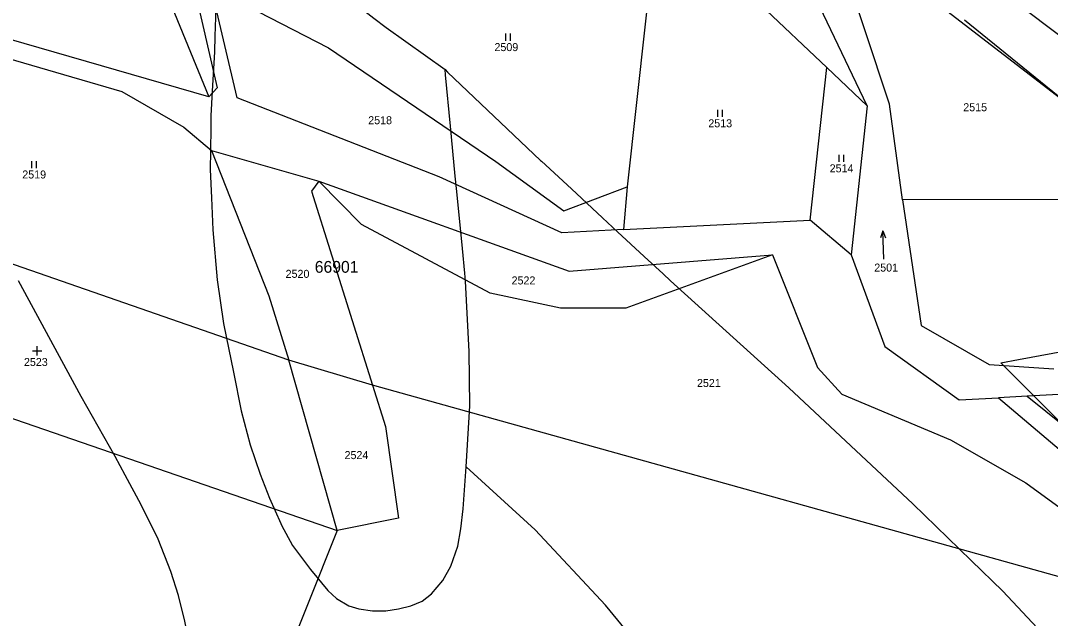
# Model space of a CAD drawing. Extents: x -546762 to -540209, y -1046851 to -1035694.
# Drawn here: x -542465 to -542246.2, y -1040002.5 to -1039875.5 of the extents above; entities that cross this region are included whole.
import ezdxf

# ---------------------------------------------------------------- set-up
doc = ezdxf.new("R2010")
doc.units = 0
for name, color, linetype in [('Vrstva 1', 7, 'Continuous'), ('Vrstva 18', 7, 'Continuous'), ('Vrstva 25', 7, 'Continuous'), ('Vrstva 52', 7, 'Continuous'), ('Vrstva 53', 7, 'Continuous')]:
    doc.layers.add(name, color=color, linetype=linetype)

msp = doc.modelspace()

# ---------------------------------------------------------------- linework, layer by layer
at = {"layer": 'Vrstva 1'}
for points in [[(-542297.11, -1039851.23), (-542216.14, -1039913.5)], [(-542330.36, -1039858.31), (-542336.15, -1039910.78)], [(-542285.16, -1039893.59), (-542302.15, -1039857.99)], [(-542430.01, -1039860.51), (-542423.31, -1039889.79)], [(-542280.4, -1039893.26), (-542290.99, -1039861.43)], [(-542435.08, -1039867.16), (-542425.03, -1039891.71)], [(-542424.58, -1039868.44), (-542399.62, -1039881.27)], [(-542419.06, -1039891.92), (-542424.58, -1039868.44)], [(-542199.5, -1039912.48), (-542254.27, -1039871.15)], [(-542307.87, -1039872.19), (-542293.78, -1039885.46)], [(-542425.03, -1039891.71), (-542480.8, -1039875.6)], [(-542482.01, -1039879.41), (-542443.54, -1039890.54)], [(-542399.62, -1039881.27), (-542364.08, -1039905.43)], [(-542297.28, -1039917.92), (-542293.78, -1039885.46)], [(-542293.78, -1039885.46), (-542285.16, -1039893.59)], [(-542443.54, -1039890.54), (-542430.37, -1039898.12)], [(-542423.31, -1039889.79), (-542425.03, -1039891.71)], [(-542376.09, -1039908.67), (-542419.06, -1039891.92)], [(-542285.16, -1039893.59), (-542288.56, -1039925.22)], [(-542277.66, -1039913.61), (-542280.4, -1039893.26)], [(-542430.37, -1039898.12), (-542424.52, -1039903.1)], [(-542424.52, -1039903.1), (-542401.65, -1039909.62)], [(-542424.52, -1039903.1), (-542412.3, -1039933.94)], [(-542364.08, -1039905.43), (-542349.61, -1039915.92)], [(-542350.04, -1039920.57), (-542376.09, -1039908.67)], [(-542408.09, -1039947.65), (-542517.77, -1039909.55)], [(-542401.65, -1039909.62), (-542403.21, -1039911.75)], [(-542401.65, -1039909.62), (-542348.46, -1039928.69)], [(-542392.65, -1039918.78), (-542401.65, -1039909.62)], [(-542349.61, -1039915.92), (-542336.15, -1039910.78)], [(-542336.15, -1039910.78), (-542336.98, -1039919.91)], [(-542403.21, -1039911.75), (-542390.31, -1039952.9)], [(-542216.14, -1039913.5), (-542277.66, -1039913.61)], [(-542277.66, -1039913.61), (-542273.7, -1039940.23)], [(-542336.98, -1039919.91), (-542297.28, -1039917.92)], [(-542288.56, -1039925.22), (-542297.28, -1039917.92)], [(-542365.28, -1039933.4), (-542392.65, -1039918.78)], [(-542336.98, -1039919.91), (-542350.04, -1039920.57)], [(-542348.46, -1039928.69), (-542305.3, -1039925.28)], [(-542305.3, -1039925.28), (-542336.46, -1039936.59)], [(-542305.3, -1039925.28), (-542295.74, -1039949.17)], [(-542288.56, -1039925.22), (-542281.4, -1039944.74)], [(-542412.3, -1039933.94), (-542408.09, -1039947.65)], [(-542350.35, -1039936.56), (-542365.28, -1039933.4)], [(-542534.56, -1039936.63), (-542397.78, -1039983.83)], [(-542336.46, -1039936.59), (-542350.35, -1039936.56)], [(-542273.7, -1039940.23), (-542259.27, -1039948.54)], [(-542281.4, -1039944.74), (-542265.61, -1039956.06)], [(-542390.31, -1039952.9), (-542408.09, -1039947.65)], [(-542397.78, -1039983.83), (-542408.09, -1039947.65)], [(-542259.27, -1039948.54), (-542245.5, -1039949.45)], [(-542295.74, -1039949.17), (-542290.56, -1039954.81)], [(-542213.14, -1040002.36), (-542390.31, -1039952.9)], [(-542390.31, -1039952.9), (-542387.55, -1039961.71)], [(-542290.56, -1039954.81), (-542267.49, -1039964.57)], [(-542244.42, -1039954.89), (-542251.17, -1039955.26)], [(-542265.61, -1039956.06), (-542257.29, -1039955.6)], [(-542251.17, -1039955.26), (-542257.29, -1039955.6)], [(-542257.29, -1039955.6), (-542223.67, -1039984.04)], [(-542251.17, -1039955.26), (-542219.78, -1039980.45)], [(-542387.55, -1039961.71), (-542384.72, -1039981.19)], [(-542267.49, -1039964.57), (-542251.47, -1039973.65)], [(-542251.47, -1039973.65), (-542216.1, -1039999.37)], [(-542384.72, -1039981.19), (-542397.78, -1039983.83)], [(-542397.78, -1039983.83), (-542416.72, -1040031.16)]]:
    msp.add_lwpolyline(points, dxfattribs=at)
at = {"layer": 'Vrstva 25'}
for p, q in [((-542361.98, -1039879.78), (-542361.98, -1039878.28)), ((-542360.98, -1039879.78), (-542360.98, -1039878.28)), ((-542316.9, -1039895.96), (-542316.9, -1039894.46)), ((-542315.9, -1039895.96), (-542315.9, -1039894.46)), ((-542291.11, -1039905.53), (-542291.11, -1039904.03)), ((-542290.11, -1039905.53), (-542290.11, -1039904.03)), ((-542462.65, -1039906.83), (-542462.65, -1039905.33)), ((-542461.65, -1039906.83), (-542461.65, -1039905.33)), ((-542462.53, -1039945.65), (-542460.53, -1039945.65)), ((-542461.53, -1039946.65), (-542461.53, -1039944.65))]:
    msp.add_line(p, q, dxfattribs=at)
for points in [[(-542281.67, -1039926.14), (-542281.85, -1039920.14), (-542282.31, -1039921.66)], [(-542281.85, -1039920.14), (-542281.31, -1039921.63)]]:
    msp.add_lwpolyline(points, dxfattribs=at)
at = {"layer": 'Vrstva 52'}
for points in [[(-542421.91, -1039840.13), (-542416.17, -1039847.54), (-542411.98, -1039852.95), (-542409.63, -1039855.66), (-542403.36, -1039862.89), (-542394.99, -1039871), (-542389.98, -1039874.97), (-542387.41, -1039877.01), (-542374.86, -1039885.9)], [(-542423.35, -1039866.85), (-542423.76, -1039878.79), (-542423.88, -1039882.17), (-542424.33, -1039890.52), (-542424.62, -1039895.77), (-542424.65, -1039898.23), (-542424.72, -1039903.2), (-542424.77, -1039907.12), (-542424.49, -1039913.18), (-542424.18, -1039919.98), (-542423.28, -1039930.59), (-542421.94, -1039939.85), (-542421.38, -1039942.6), (-542419.84, -1039950.17), (-542418.2, -1039958.38), (-542416.26, -1039965.6), (-542414.13, -1039971.83), (-542412.17, -1039976.96), (-542409.78, -1039982.34), (-542409.62, -1039982.64), (-542407.3, -1039986.95), (-542403.46, -1039992.07), (-542399.79, -1039996.51), (-542397.95, -1039998.23), (-542395.32, -1039999.79), (-542393.92, -1040000.21), (-542393.17, -1040000.43)], [(-542201.89, -1040004.43), (-542202.94, -1040001.27), (-542204.29, -1040000), (-542216.78, -1039988.21), (-542217.91, -1039987.15), (-542219.57, -1039985.58), (-542220.27, -1039984.88), (-542223.54, -1039981.6), (-542233.42, -1039971.67), (-542237.25, -1039967.82), (-542238.45, -1039966.61), (-542250.49, -1039954.52), (-542252.4, -1039952.6), (-542256.81, -1039948.17), (-542253.01, -1039947.47), (-542224.62, -1039942.22), (-542192.94, -1039938), (-542215.11, -1039925.2), (-542215.97, -1039917.69), (-542216.44, -1039913.53), (-542233.34, -1039900.68), (-542264.49, -1039875.43)], [(-542370.35, -1039970.31), (-542369.72, -1039959.71), (-542369.58, -1039957.33), (-542369.75, -1039945.8), (-542370.52, -1039930.86), (-542370.69, -1039929.13), (-542371.19, -1039923.94), (-542372.02, -1039915.35), (-542372.42, -1039911.19), (-542372.68, -1039908.54), (-542373.7, -1039897.92), (-542374.75, -1039887), (-542374.86, -1039885.9)], [(-542374.86, -1039885.9), (-542374.31, -1039886.43), (-542354.56, -1039905.23), (-542354.39, -1039905.39), (-542348.03, -1039911.27), (-542341.38, -1039917.42), (-542338.2, -1039920.36), (-542332.54, -1039925.59), (-542328.55, -1039929.28), (-542326.95, -1039930.76), (-542301.85, -1039953.51), (-542275.45, -1039978.1), (-542263.06, -1039990.16), (-542256.37, -1039996.66), (-542247.99, -1040005.62)], [(-542439.25, -1040043.78), (-542436.44, -1040040.59), (-542434.9, -1040038.83), (-542432.76, -1040035.67), (-542430.71, -1040031.49), (-542429.35, -1040027.39), (-542428.58, -1040022.52), (-542428.32, -1040017.48), (-542428.41, -1040013.04), (-542429.01, -1040008.6), (-542430.12, -1040003.05), (-542431.48, -1039997.58), (-542433.15, -1039992.51), (-542435.84, -1039985.63), (-542439.43, -1039978.31), (-542442.8, -1039972.06), (-542444.95, -1039968.08), (-542452.16, -1039955.34), (-542465.49, -1039930.76)], [(-542390.15, -1040000.87), (-542387.42, -1040000.82), (-542384.73, -1040000.43), (-542382.15, -1039999.79), (-542379.71, -1039998.77), (-542377.71, -1039997.21), (-542375.32, -1039994.43), (-542373.61, -1039991.4), (-542372.15, -1039987.15), (-542371.51, -1039983.45), (-542371.03, -1039979.2), (-542370.35, -1039970.31)], [(-542306.59, -1040042.52), (-542328.37, -1040014.72), (-542340.77, -1039999.63), (-542355.7, -1039983.63), (-542370.35, -1039970.31)], [(-542393.17, -1040000.43), (-542390.29, -1040000.87), (-542390.15, -1040000.87)]]:
    msp.add_lwpolyline(points, dxfattribs=at)

# ---------------------------------------------------------------- texts
at = {"layer": 'Vrstva 18'}
for s, p in [('2509', (-542364.37, -1039881.99)), ('2515', (-542264.76, -1039894.76)), ('2518', (-542391.19, -1039897.52)), ('2513', (-542318.93, -1039898.17)), ('2514', (-542293.15, -1039907.74)), ('2519', (-542464.69, -1039909.04)), ('2520', (-542408.74, -1039930.14)), ('2501', (-542283.67, -1039928.81)), ('2522', (-542360.73, -1039931.54)), ('2523', (-542464.34, -1039948.86)), ('2521', (-542321.34, -1039953.32)), ('2524', (-542396.22, -1039968.63))]:
    msp.add_text(s, height=1.7, dxfattribs=at).set_placement(p)
at = {"layer": 'Vrstva 53'}
msp.add_text('66901', height=2.5, dxfattribs=at).set_placement((-542402.55, -1039929.06))

doc.saveas('drawing.dxf')
